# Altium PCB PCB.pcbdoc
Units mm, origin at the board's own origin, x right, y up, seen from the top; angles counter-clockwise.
Board outline 45.92 x 42.7 mm, 2 copper layers (Top Layer, Bottom Layer); 13 components, 6 nets, 30 pads, 10 vias.
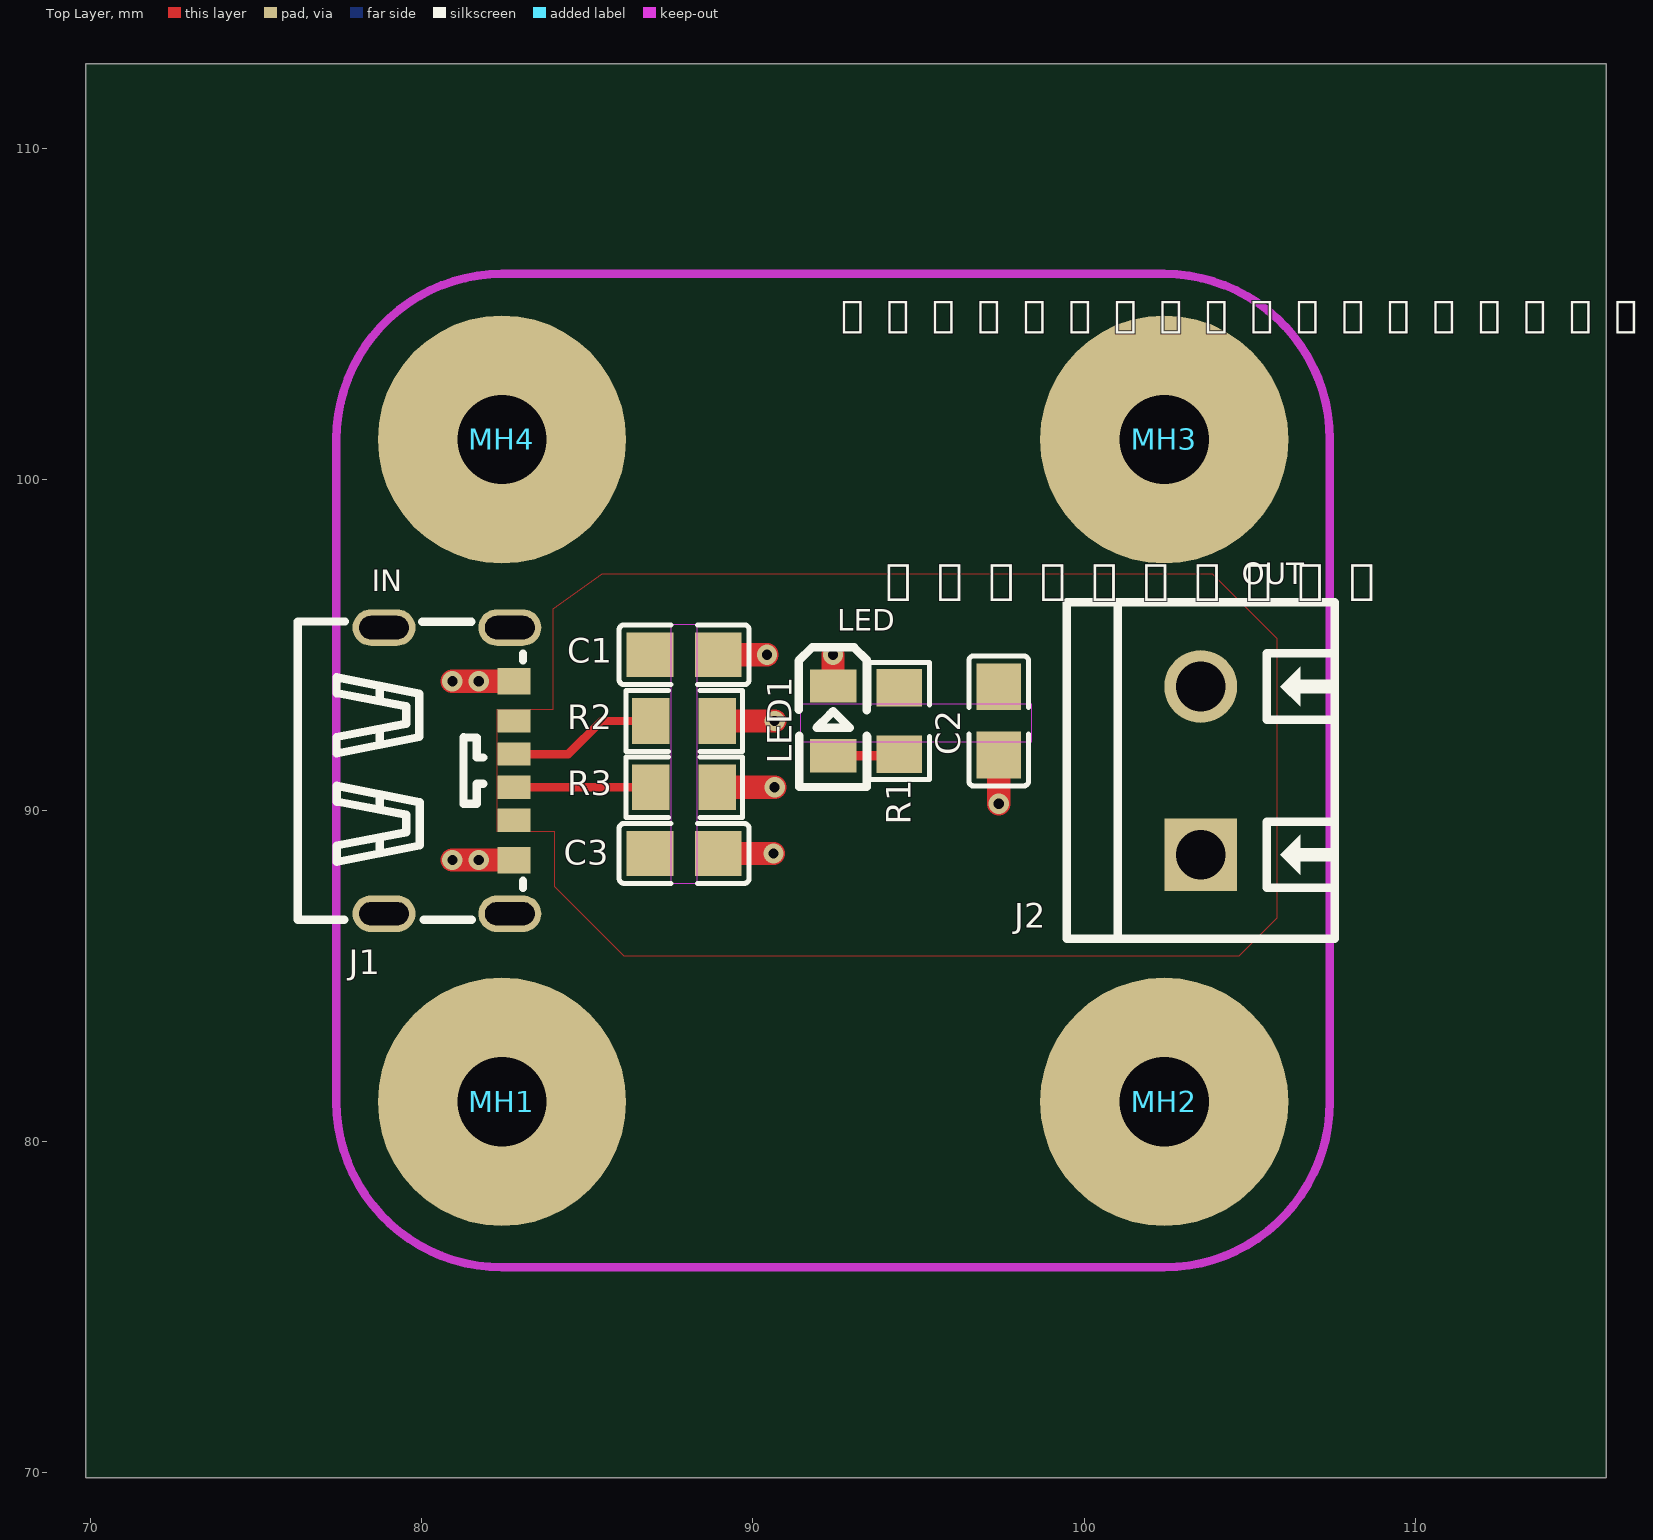
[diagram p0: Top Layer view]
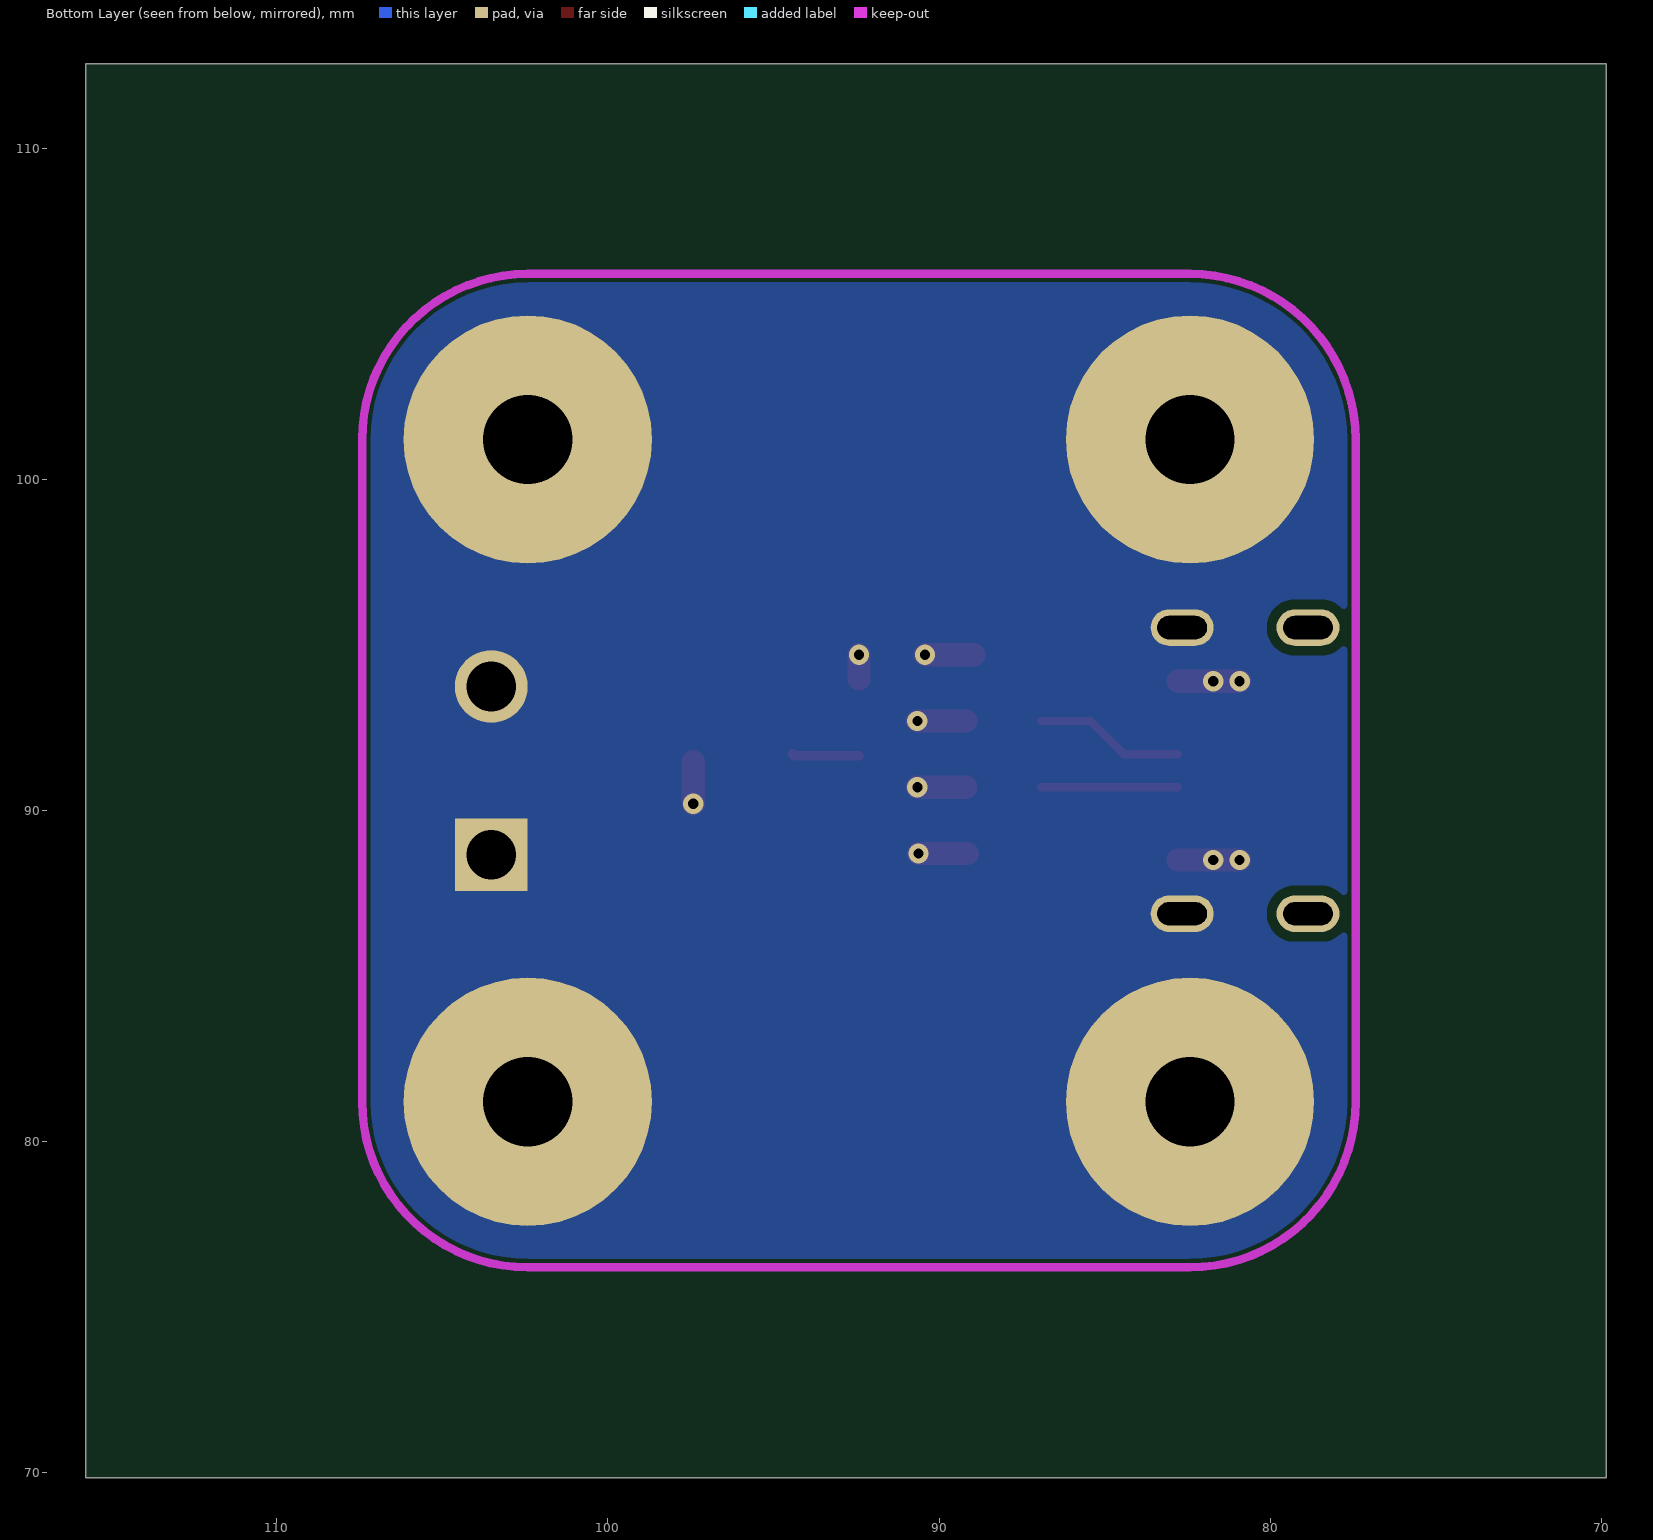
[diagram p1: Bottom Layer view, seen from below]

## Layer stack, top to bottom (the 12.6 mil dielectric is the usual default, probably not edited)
Top Layer: signal copper (thickness not stored)
Dielectric: dielectric 0.32, FR-4, Dk 4.8
Bottom Layer: signal copper (thickness not stored)

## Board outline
115.772,69.85 69.85,69.85 69.85,112.55 115.772,112.55

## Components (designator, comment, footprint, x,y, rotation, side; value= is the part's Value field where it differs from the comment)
C1 "CC0805KRX7R9BB104" C0805 87.922,94.7 r180 top
C2 "CC0805KRX7R9BB104" C0805 97.422,92.7 r90 top
C3 "CC0805KRX7R9BB104" C0805 87.922,88.7 r180 top
J1 "TYPE-C 6P(073)" TYPE-C-SMD_TYPE-C-6P 80.822,91.2 r270 top
J2 "MKDSN 1,5/ 2-5,08" CONN-TH_2P-P5.08_1729128 103.522,91.2 r90 top
LED1 "KT-0805G" LED0805-R-RD 92.422,92.7 r270 top
MH1 "MH_7.5x2.7MM" MH_7.5X2.7MM 82.422,81.2 r0 top
MH2 "MH_7.5x2.7MM" MH_7.5X2.7MM 102.422,81.2 r0 top
MH3 "MH_7.5x2.7MM" MH_7.5X2.7MM 102.422,101.2 r0 top
MH4 "MH_7.5x2.7MM" MH_7.5X2.7MM 82.422,101.2 r0 top
R1 "0805W8F1001T5E" R0805 94.422,92.7 r90 top
R2 "0805W8F5101T5E" R0805 87.922,92.7 r180 top
R3 "0805W8F5101T5E" R0805 87.922,90.7 r180 top

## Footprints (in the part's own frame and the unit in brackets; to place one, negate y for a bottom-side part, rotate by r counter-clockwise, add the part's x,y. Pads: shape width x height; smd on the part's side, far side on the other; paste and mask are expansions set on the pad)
C0805 [mm]
  rect 1.41x1.35 smd: 1(-1.03,0) 2(1.03,0)
  silkscreen extent -1.96,-0.9 1.96,0.9
CONN-TH_2P-P5.08_1729128 [mm]
  rect 2.2x2.2 hole 1.5: 1(-2.54,0)
  round 2.2 hole 1.5: 2(2.54,0)
  silkscreen extent -5.08,-4.05 5.08,4.05
LED0805-R-RD [mm]
  rect 1x1.4 smd: 1(1.05,0) 2(-1.05,0)
  silkscreen extent -2.22,-1.04 1.99,1.01
MH_7.5X2.7MM [mm]
  round 7.5 hole 2.7: 1(0,0)
R0805 [mm]
  rect 1.133x1.377 smd: 1(-1,0) 2(1,0)
  silkscreen extent -1.76,-0.92 1.76,0.92
TYPE-C-SMD_TYPE-C-6P [mm]
  oval 1.1x1.9 hole 0.7 slot 1.5 at 90 deg: 7(-4.32,-1.963) 7(-4.32,1.838) 7(4.32,-1.963) 7(4.32,1.838)
  rect 0.7x1 smd: A5(-0.5,1.963) A9(1.5,1.963) B5(0.5,1.963) B9(-1.5,1.963)
  rect 0.8x1 smd: A12(2.7,1.963) B12(-2.7,1.963)
  silkscreen extent -4.5,-4.56 4.5,2.24

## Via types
v1: diameter 0.61, hole 0.305, Top Layer to Bottom Layer, 10 vias

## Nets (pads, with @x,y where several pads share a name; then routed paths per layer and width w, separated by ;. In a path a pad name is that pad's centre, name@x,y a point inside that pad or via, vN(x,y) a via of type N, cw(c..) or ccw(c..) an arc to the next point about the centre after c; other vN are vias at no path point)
+5V: C1.2 C2.2 C3.2 J1.A9 J1.B9 J2.2 R1.2
CC1: J1.B5 R3.2 | length 4.1
  Top Layer w0.254: J1.B5 R3.2
CC2: J1.A5 R2.2 | length 4.6
  Top Layer w0.254: J1.A5 84.422,91.7 85.422,92.7 R2.2
DIODE: LED1.1 R1.1 | length 2
  Top Layer w0.3: LED1.1 94.372,91.65 R1.1
GND: C1.1 C2.1 C3.1 J1.7 J1.A12 J1.B12 J2.1 LED1.2 MH1.1 MH2.1 MH3.1 MH4.1 R2.1 R3.1 | length 11.6
  Top Layer w0.7: v1(80.922,88.5) 81.791,88.5 J1.A12 ; v1(80.922,93.9) 81.791,93.9 J1.B12 ; C1.1 v1(90.422,94.7) ; C3.1@89.151,88.7 v1(90.621,88.7) ; R3.1@89.187,90.7 v1(90.657,90.7) ; R2.1@89.187,92.7 v1(90.657,92.7) ; LED1.2@92.422,93.965 v1(92.422,94.7) ; v1(97.422,90.2) C2.1@97.422,91.471
  other v1: 81.722,88.5 81.722,93.9
"": 

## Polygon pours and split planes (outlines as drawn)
GND on Bottom Layer (solid, remove dead copper, pour order 0): 77.422,76.2 109.422,76.2 109.422,106.2 77.422,106.2
+5V on Top Layer (solid, remove dead copper, pour order 2): 83.978,96.092 85.454,97.148 103.875,97.148 105.822,95.2 105.822,86.75 104.672,85.6 86.122,85.6 84.022,87.7 84.022,89.35 82.28,89.35 82.28,93.05 83.978,93.05

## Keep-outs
Top Layer:
  region net "": 87.521,87.796 88.324,87.796 88.324,95.604 87.521,95.604
  region net "": 91.422,92.071 98.422,92.071 98.422,93.2 91.422,93.2
Board Outline Layer:
  lines w0.254 net "": 77.422,81.2 ccw(c82.422,81.2) 82.422,76.2 102.422,76.2 ccw(c102.422,81.2) 107.422,81.2 107.422,101.2 ccw(c102.422,101.2) 102.422,106.2 82.422,106.2 ccw(c82.422,101.2) 77.422,101.2 77.422,81.2

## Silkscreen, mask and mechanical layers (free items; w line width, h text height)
Top Silkscreen Layer:
  text "SYSKIDO[윤기도]2024.03.10" at 92.322,104.4 h1
  text "OUT" at 104.767,96.822 h0.65
  text "IN" at 78.496,96.622 h0.65
  text "POWER[윤기도]" at 93.615,96.309 h1.13
  text "LED" at 92.553,95.422 h0.65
